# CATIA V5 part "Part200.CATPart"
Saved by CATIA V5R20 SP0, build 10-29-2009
Part number: 9FA 168712
Revision: ANY
Definition: UNKNOWN
Nomenclature: 9FA 168712
Source: Unknown
Bounding box of the stored display mesh (mm): x -8 to 8, y 0.13 to 20.13, z -8 to 8
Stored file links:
  C:\Users\Utente\Desktop\IO LAVORO\3D X SITO CF\CUMSA\3D files FA\FA 168712-20\Part200.CATPart

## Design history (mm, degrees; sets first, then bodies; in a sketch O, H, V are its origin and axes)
Body1 "Cortar-Extruir4" (main body)
  Solid1: solid without history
